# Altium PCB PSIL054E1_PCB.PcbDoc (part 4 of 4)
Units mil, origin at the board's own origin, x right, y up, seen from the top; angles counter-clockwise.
Board outline 2080 x 2700 mil, 8 copper layers (SSTXRX1, GND Plane 1, High Speed, GND Plane 2, Power 1, Power 2, GND Plane 3, SSTXRX2), stack 58.12 mil thick; 247 components, 148 nets, 834 pads, 632 vias.
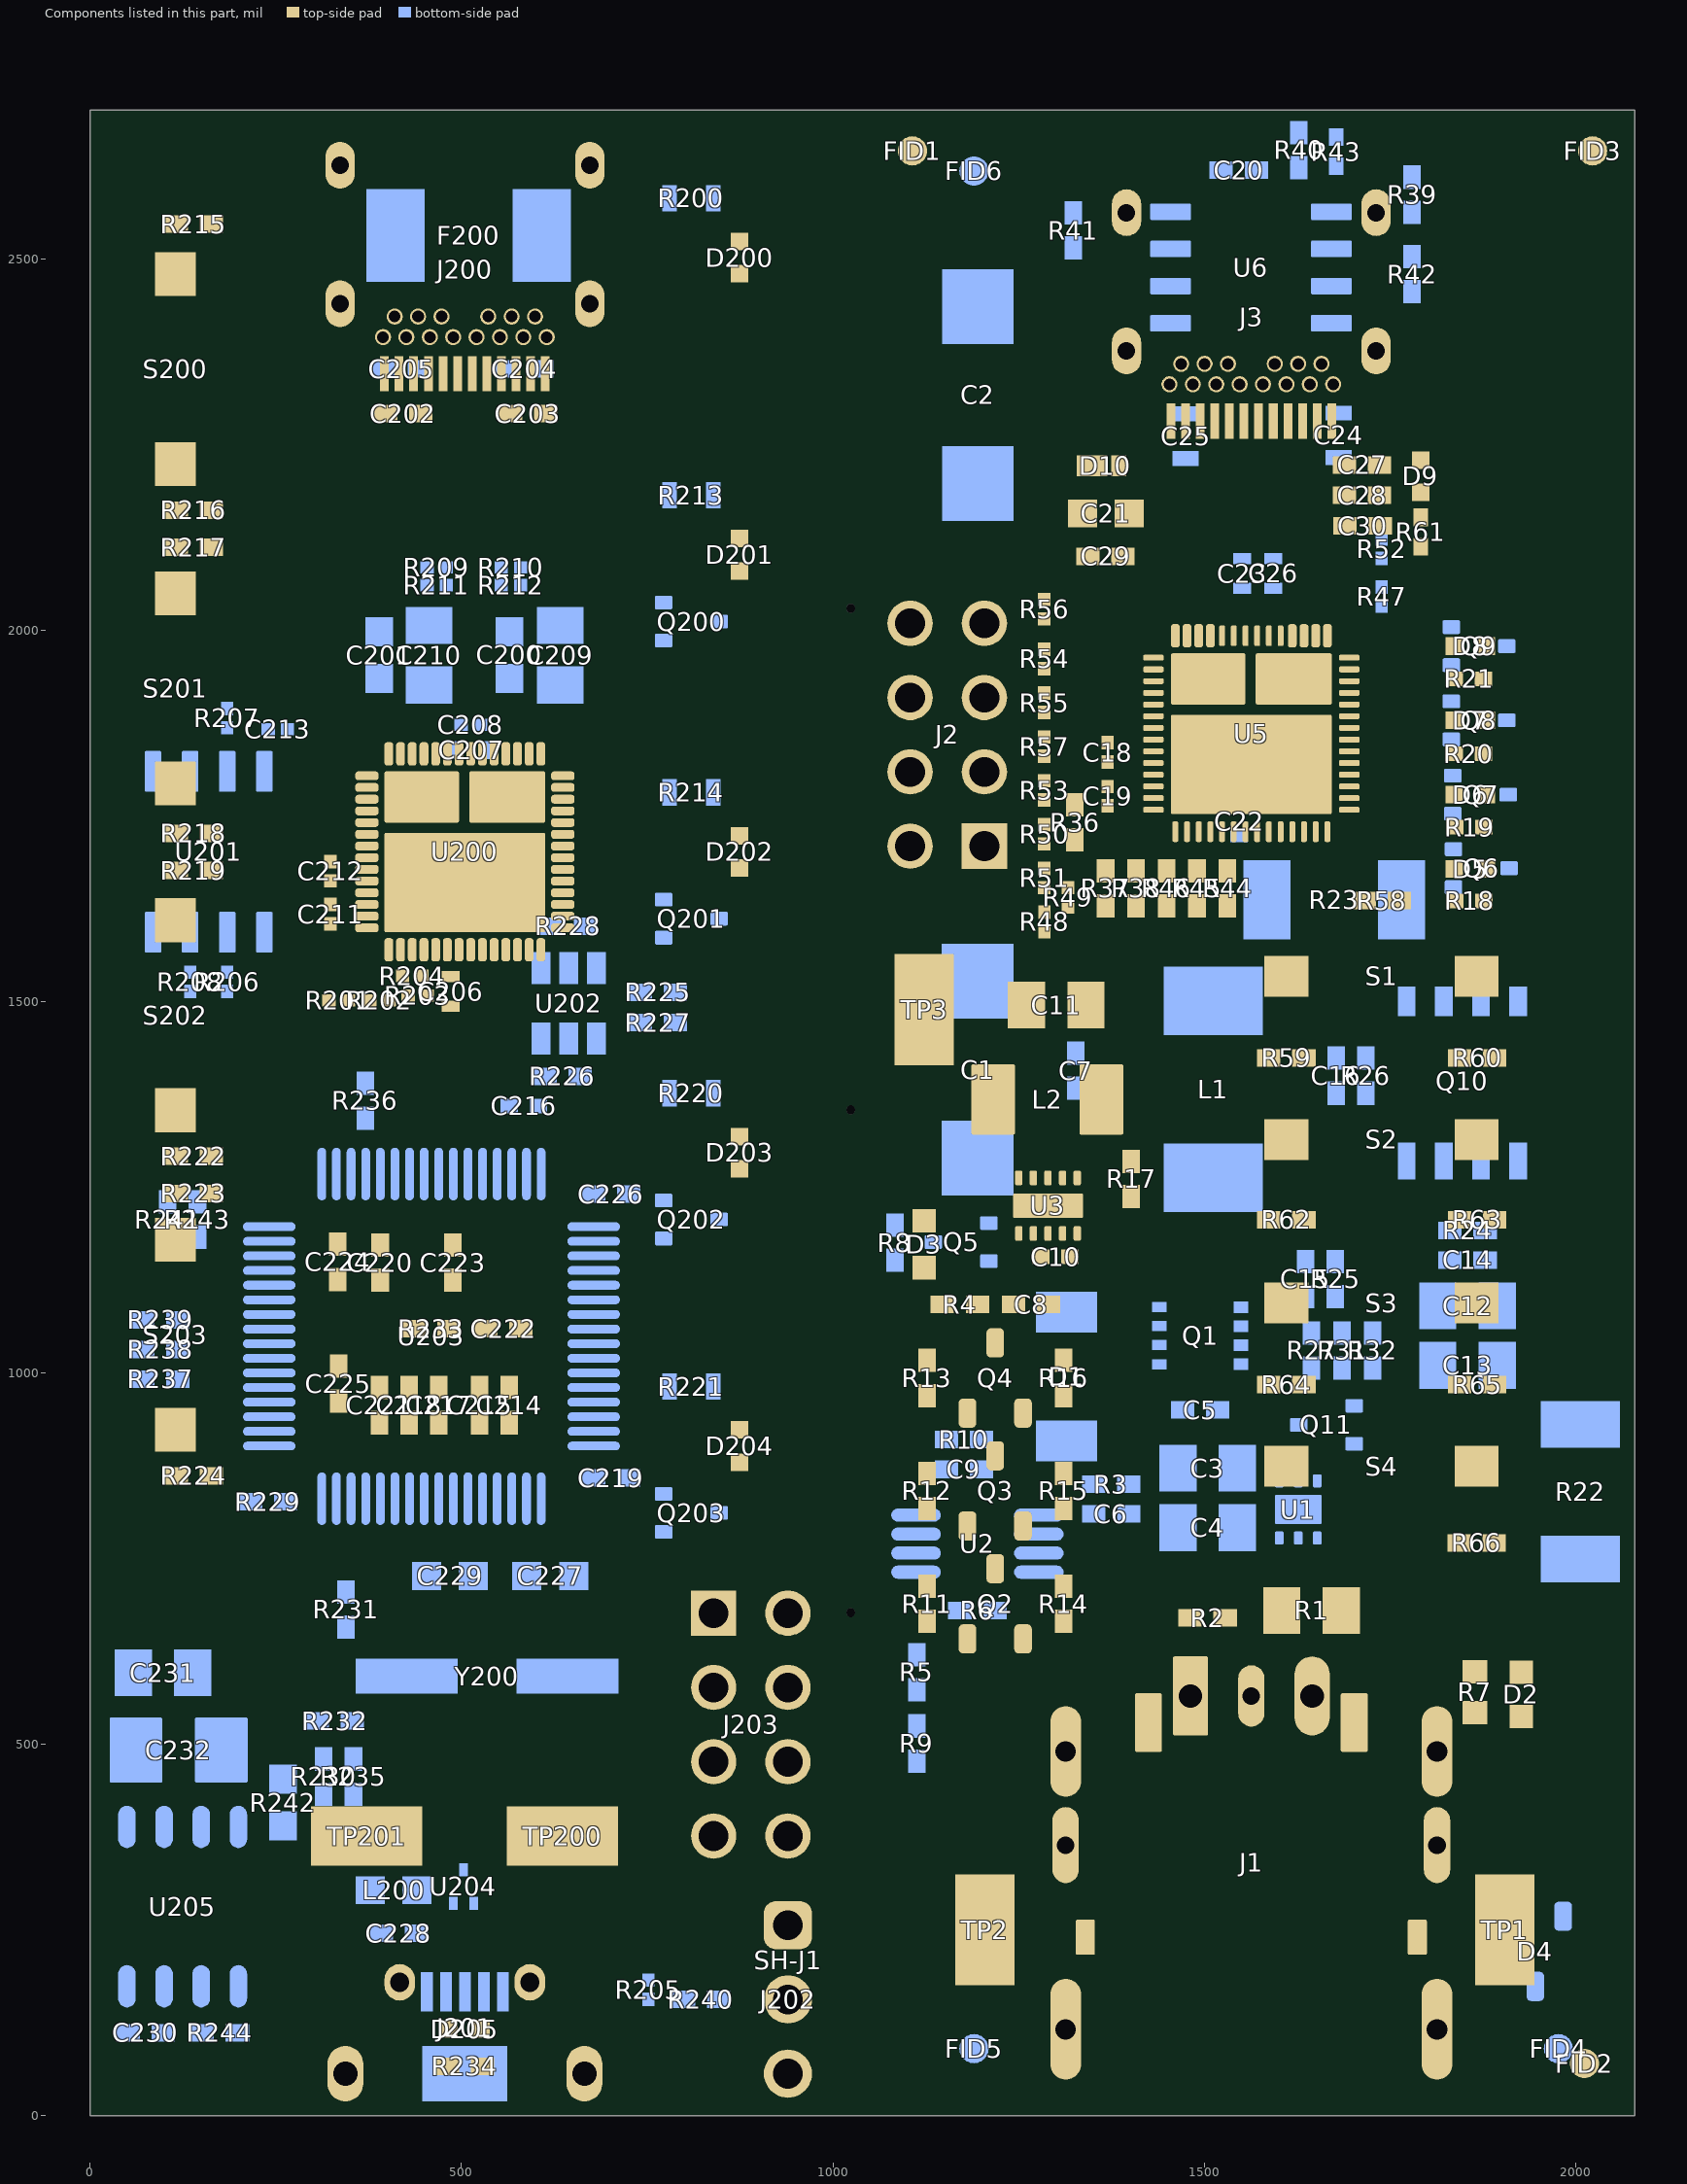
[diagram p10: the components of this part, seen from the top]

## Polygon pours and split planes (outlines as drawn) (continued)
P3V3_SINK on Power 1 "POWER_1_P3V3_SINK_P162" (solid, remove dead copper, pour order 162): 235.45,1211.31 412.45,1388.31 579.45,1388.31 634.45,1333.31 634.45,906.31 251.45,906.31 235.45,922.31
P3V3_SINK on Power 1 "POWER_1_P3V3_SINK_P160" (solid, remove dead copper, pour order 160): 14.45,641.31 0,655.75 0,2663.86 36.14,2700 970,2700 1000,2670 1000,1528.86 902.45,1431.31 819.45,1431.31 803.45,1447.31 804.45,1448.31 804.45,2411.31 758.45,2457.31 364.45,2457.31 228.45,2593.31 135.45,2593.31 113,2570.86 113,647.47
GND on High Speed "HIGH_SPEED_GND_P188" (solid, remove dead copper, pour order 188): 0,2700 2080,2700 2080,0 0,0
SYS_PWR on High Speed "HIGH_SPEED_SYS_PWR_P082" (solid, remove dead copper, pour order 82): 1365,732 2072,732 2072,636 1914,478 1365,478
NetC12_1 on High Speed "HIGH_SPEED_NETC12_1_P076" (solid, remove dead copper, pour order 76): 1877,1529.93 2004.66,1529.93 2072,1462.59 2072,889.93 1894.66,889.93 1877,907.59 1877,1203.93
PP_HV on High Speed "HIGH_SPEED_PP_HV_P062" (solid, remove dead copper, pour order 62): 1436,1456 1159.79,1456 1055,1560.79 1055,2181 1615.26,2181 1647.1,2149.16 1692.35,2149.16 1754.37,2087.13 1754.37,1966.76 1386.51,1966.76 1372.75,1953 1376,1949.75 1376,1838 1436,1778
VREGOUT on High Speed "HIGH_SPEED_VREGOUT_P182" (solid, remove dead copper, pour order 182): 694.45,816.31 689.45,811.31 459.45,811.31 378.64,892.12 378.64,1200.5 459.45,1281.31 689.45,1281.31 694.45,1276.31
VBUS_SINK on High Speed "HIGH_SPEED_VBUS_SINK_P180" (solid, remove dead copper, pour order 180): 557.45,2208.31 663.45,2102.31 663.45,1825.31 646.45,1808.31 209.45,1808.31 183.45,1834.31 183.45,1980.31 411.45,2208.31
VBUS_SINK on High Speed "HIGH_SPEED_VBUS_SINK_P178" (solid, remove dead copper, pour order 178): 219.45,2389.31 219.45,2657.31 262.14,2700 750.75,2700 851.45,2599.31 851.45,2139.31 825.45,2113.31 716.45,2113.31 624.45,2205.31 624.45,2420.31 584.45,2460.31 380.45,2460.31 328.45,2408.31 329.45,2407.31 329.45,2263.31 270.45,2204.31 235.45,2204.31 218.45,2221.31
GND on Power 2 "POWER_2_GND_P184" (solid, remove dead copper, pour order 184): 0,2700 2080,2700 2080,0 0,0
SYS_PWR on Power 2 "POWER_2_SYS_PWR_P078" (solid, remove dead copper, pour order 78): 1365,732 2072,732 2072,636 1914,478 1365,478
NetC12_1 on Power 2 "POWER_2_NETC12_1_P072" (solid, remove dead copper, pour order 72): 1877,1529.93 2004.66,1529.93 2072,1462.59 2072,889.93 1894.66,889.93 1877,907.59 1877,1203.93
PP_HV on Power 2 "POWER_2_PP_HV_P058" (solid, remove dead copper, pour order 58): 1436,1456 1159.79,1456 1055,1560.79 1055,2181 1615.26,2181 1647.1,2149.16 1692.35,2149.16 1754.37,2087.13 1754.37,1966.76 1386.51,1966.76 1372.75,1953 1376,1949.75 1376,1838 1436,1778
PP_HV_SINK on Power 2 "POWER_2_PP_HV_SINK_P174" (solid, remove dead copper, pour order 174): 810.45,1719.31 810.45,2075.31 709.45,2176.31 419.45,2176.31 254.45,2011.31 254.45,1719.31
PP_HV_SINK on Power 2 "POWER_2_PP_HV_SINK_P172" (solid, remove dead copper, pour order 172): 797.75,1823 866.45,1754.31 866.45,448.31 714.45,296.31 124.45,296.31 0,420.75 0,1621.86 201.14,1823
FUSE_VBUS on Power 2 "POWER_2_FUSE_VBUS_P170" (solid, remove dead copper, pour order 170): 750.75,2700 881.45,2569.31 881.45,2316.31 827.45,2262.31 106.45,2262.31 47.45,2321.31 47.45,2589.31 158.14,2700
GND on GND Plane 1 (split plane): 2059.9,20.1 1788.32,20.1 1788.32,466.47 1788.32,469.6 1787.94,473.52 1786.79,477.29 1784.39,483.08 1782.54,486.55 1780.04,489.6 1775.61,494.03 1772.56,496.53 1769.09,498.38 1763.3,500.78 1759.53,501.92 1755.61,502.31 1752.48,502.31 1374.52,502.31 1371.39,502.31 1367.47,501.92 1363.7,500.78 1357.91,498.38 1354.44,496.53 1351.39,494.03 1346.96,489.6 1346.07,488.5 1344.46,486.55 1342.61,483.08 1340.21,477.29 1339.87,476.17 1339.07,473.52 1338.81,470.88 1338.68,469.6 1338.68,466.47 1338.68,20.1 1046.15,20.1 1048.21,21.79 1050.71,24.83 1052.57,28.31 1053.71,32.08 1054.1,36 1054.1,641 1053.71,644.92 1052.57,648.69 1050.71,652.17 1048.21,655.21 1045.17,657.71 1041.69,659.57 1037.92,660.71 1034,661.1 1014,661.1 1010.08,660.71 1006.31,659.57 1002.83,657.71 999.79,655.21 997.29,652.17 995.43,648.69 994.29,644.92 993.9,641 993.9,36 994.29,32.08 995.43,28.31 997.29,24.83 999.79,21.79 1001.85,20.1 20.1,20.1 20.1,2679.9 998.72,2679.9 997.29,2678.17 995.43,2674.69 994.29,2670.92 993.9,2667 993.9,2062 994.29,2058.08 995.43,2054.31 997.29,2050.83 999.79,2047.79 1002.83,2045.29 1006.31,2043.43 1010.08,2042.29 1014,2041.9 1034,2041.9 1037.92,2042.29 1041.69,2043.43 1045.17,2045.29 1048.21,2047.79 1050.71,2050.83 1052.57,2054.31 1053.71,2058.08 1054.1,2062 1054.1,2667 1053.71,2670.92 1052.57,2674.69 1050.71,2678.17 1049.28,2679.9 2059.9,2679.9
GND on GND Plane 2 (split plane): 2059.9,20.1 1788.32,20.1 1788.32,466.47 1788.32,469.6 1787.94,473.52 1786.79,477.29 1784.39,483.08 1782.54,486.55 1780.04,489.6 1775.61,494.03 1772.56,496.53 1769.09,498.38 1763.3,500.78 1759.53,501.92 1755.61,502.31 1752.48,502.31 1374.52,502.31 1371.39,502.31 1367.47,501.92 1363.7,500.78 1357.91,498.38 1354.44,496.53 1351.39,494.03 1346.96,489.6 1346.07,488.5 1344.46,486.55 1342.61,483.08 1340.21,477.29 1339.87,476.17 1339.07,473.52 1338.81,470.88 1338.68,469.6 1338.68,466.47 1338.68,20.1 1046.15,20.1 1048.21,21.79 1050.71,24.83 1052.57,28.31 1053.71,32.08 1054.1,36 1054.1,641 1053.71,644.92 1052.57,648.69 1050.71,652.17 1048.21,655.21 1045.17,657.71 1041.69,659.57 1037.92,660.71 1034,661.1 1014,661.1 1010.08,660.71 1006.31,659.57 1002.83,657.71 999.79,655.21 997.29,652.17 995.43,648.69 994.29,644.92 993.9,641 993.9,36 994.29,32.08 995.43,28.31 997.29,24.83 999.79,21.79 1001.85,20.1 20.1,20.1 20.1,2679.9 998.72,2679.9 997.29,2678.17 995.43,2674.69 994.29,2670.92 993.9,2667 993.9,2062 994.29,2058.08 995.43,2054.31 997.29,2050.83 999.79,2047.79 1002.83,2045.29 1006.31,2043.43 1010.08,2042.29 1014,2041.9 1034,2041.9 1037.92,2042.29 1041.69,2043.43 1045.17,2045.29 1048.21,2047.79 1050.71,2050.83 1052.57,2054.31 1053.71,2058.08 1054.1,2062 1054.1,2667 1053.71,2670.92 1052.57,2674.69 1050.71,2678.17 1049.28,2679.9 2059.9,2679.9
GND on GND Plane 3 (split plane): 2059.9,20.1 1788.32,20.1 1788.32,466.47 1788.32,469.6 1787.94,473.52 1786.79,477.29 1784.39,483.08 1782.54,486.55 1780.04,489.6 1775.61,494.03 1772.56,496.53 1769.09,498.38 1763.3,500.78 1759.53,501.92 1755.61,502.31 1752.48,502.31 1374.52,502.31 1371.39,502.31 1367.47,501.92 1363.7,500.78 1357.91,498.38 1354.44,496.53 1351.39,494.03 1346.96,489.6 1346.07,488.5 1344.46,486.55 1342.61,483.08 1340.21,477.29 1339.87,476.17 1339.07,473.52 1338.81,470.88 1338.68,469.6 1338.68,466.47 1338.68,20.1 1046.15,20.1 1048.21,21.79 1050.71,24.83 1052.57,28.31 1053.71,32.08 1054.1,36 1054.1,641 1053.71,644.92 1052.57,648.69 1050.71,652.17 1048.21,655.21 1045.17,657.71 1041.69,659.57 1037.92,660.71 1034,661.1 1014,661.1 1010.08,660.71 1006.31,659.57 1002.83,657.71 999.79,655.21 997.29,652.17 995.43,648.69 994.29,644.92 993.9,641 993.9,36 994.29,32.08 995.43,28.31 997.29,24.83 999.79,21.79 1001.85,20.1 20.1,20.1 20.1,2679.9 998.72,2679.9 997.29,2678.17 995.43,2674.69 994.29,2670.92 993.9,2667 993.9,2062 994.29,2058.08 995.43,2054.31 997.29,2050.83 999.79,2047.79 1002.83,2045.29 1006.31,2043.43 1010.08,2042.29 1014,2041.9 1034,2041.9 1037.92,2042.29 1041.69,2043.43 1045.17,2045.29 1048.21,2047.79 1050.71,2050.83 1052.57,2054.31 1053.71,2058.08 1054.1,2062 1054.1,2667 1053.71,2670.92 1052.57,2674.69 1050.71,2678.17 1049.28,2679.9 2059.9,2679.9

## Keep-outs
Keep-Out Layer:
  text ".Layer_Name" at 577,-858.49 h60

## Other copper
SSTXRX1:
  rectangle net SYS_PWR: 1859.66,170.93 1948.66,434.93
  rectangle net GND: 1159.66,168.93 1249.66,435.93
  rectangle net GND: 1650.1,1785.26 1703.1,1827.26
  region net P3V3: 1172.66,1563.93 1092.66,1563.93 1092.66,1345.93 1172.66,1345.93
  rectangle net SYS_PWR: 1259.66,1144.93 1295.66,1202.93
  rectangle net GND: 1304.66,1144.93 1339.66,1240.93
  region net NetD205_2: 514.45,128.12 514.45,54.31 544.45,54.31 544.45,128.12
  region net NetD204_1: 858.7,999.31 858.7,919.31 890.45,919.31 890.45,999.31
  region net NetD203_1: 858.7,1394.31 858.7,1315.31 890.45,1315.31 890.45,1394.31
  region net NetD202_1: 858.7,1799.31 858.7,1719.31 890.45,1719.31 890.45,1799.31
  region net NetD201_1: 858.7,2199.31 858.7,2119.31 890.45,2119.31 890.45,2199.31
  region net NetD200_1: 858.7,2600.31 858.7,2519.31 890.45,2519.31 890.45,2600.31
  region net GND: 598.45,1668.31 598.45,1624.31 652.45,1624.31 652.45,1668.31
  region net LDO_3V3_SINK: 144.45,1261.31 144.45,1221.31 209.45,1221.31 209.45,1261.31
  region net LDO_3V3_SINK: 144.45,1696.31 144.45,1656.31 209.45,1656.31 209.45,1696.31
  region net LDO_3V3_SINK: 144.45,2131.31 144.45,2091.31 209.45,2091.31 209.45,2131.31
  region net LDO_3V3_SINK: 144.45,2566.31 144.45,2526.31 209.45,2526.31 209.45,2566.31
  text ".Layer_Name" at 577,-859.49 h60
High Speed:
  text ".Layer_Name" at 577,-858.49 h60
Power 1:
  text ".Layer_Name" at 577,-859.49 h60
Power 2:
  text ".Layer_Name" at 577,-858.49 h60
SSTXRX2:
  rectangle net DRAIN2: 1572,1899 1675,1968
  rectangle net DRAIN1: 1461,1897 1563,1968
  rectangle net Drain2_SINK: 515,1745 610,1805
  rectangle net Drain1_SINK: 400,1745 495,1805
  region net F_I2C1_SDA: 209.45,1117.88 209.45,1096.31 274.45,1096.31 274.45,1117.88
  region net VBUS_SINK: 746.45,2599.31 746.45,2563.31 789.45,2563.31 789.45,2599.31
  region net NetD200_1: 828.45,2599.31 828.45,2563.31 882.45,2563.31 882.45,2599.31
  region net NetD201_1: 829.45,2199.31 829.45,2163.31 882.45,2163.31 882.45,2199.31
  region net LDO_3V3_SINK: 746.45,2199.31 746.45,2163.31 790.45,2163.31 790.45,2199.31
  region net NetD202_1: 828.45,1799.31 828.45,1763.31 882.45,1763.31 882.45,1799.31
  region net LDO_3V3_SINK: 746.45,1799.31 746.45,1763.31 790.45,1763.31 790.45,1799.31
  region net LDO_3V3_SINK: 746.45,1394.31 746.45,1358.31 790.45,1358.31 790.45,1394.31
  region net NetD203_1: 828.45,1394.31 828.45,1358.31 882.45,1358.31 882.45,1394.31
  region net NetD204_1: 828.45,999.31 828.45,963.31 882.45,963.31 882.45,999.31
  region net LDO_3V3_SINK: 746.45,999.31 746.45,963.31 789.45,963.31 789.45,999.31
  text ".Layer_Name" at 577,-858.49 h60
  text ".Layer_Name" at 577,-859.49 h60
GND Plane 1 (plane layer: these items are gaps in the copper):
  text ".Layer_Name" at 577,-858.49 h60
GND Plane 2 (plane layer: these items are gaps in the copper):
  text ".Layer_Name" at 577,-858.49 h60
GND Plane 3 (plane layer: these items are gaps in the copper):
  text ".Layer_Name" at 577,-858.49 h60

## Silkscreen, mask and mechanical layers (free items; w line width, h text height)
Top Overlay:
  lines w10: 4.45,751.31 997,751 ; 859,155 859,14 939,14 ; 897,156 859,156 859,300 938,300
  text "TIDA-050012" at 1177,2671 h100 r270
  text "VBUS" at 919.45,2621.31 h100 r270
  text "D5 - D8: Output Voltage / S1 - S4: Source Voltage Select" at 1915,2577 h50 r270
  text "5V" at 205,2405 h100 r270
  text "VBUS" at 1852,2248 h60 r270
  text "5V" at 915,2140 h100 r270
  text "D200 - D203: Input Voltage / S200 - S203: Sink Voltage Select" at 666,2130 h50 r270
  text "20V" at 1918,2049 h70 r270
  text "9V" at 204.45,1971.31 h100 r270
  text "15V" at 1919,1930 h70 r270
  text "9V" at 1919,1811 h70 r270
  text "9V" at 915,1740 h100 r270
  text "5V" at 1919,1715 h70 r270
  text "5V" at 1937,1588 h100 r270
  text "15V" at 204.45,1571.31 h100 r270
  text "3.3V" at 1101,1389 h60 r270
  text "9V" at 1937,1363 h100 r270
  text "15V" at 915,1360 h100 r270
  text "DC/DC Output" at 1062,1295 h30 r270
  text "15V" at 1936,1170 h100 r270
  text "20V" at 205,1120 h100 r270
  text "20V" at 915,960 h100 r270
  text "20V" at 1935,956 h100 r270
  text "PPHV" at 610,685 h100 r270
  text "TIDA-050014" at 93,666 h100 r270
  text "GND" at 342,636 h100 r270
  text "SYS_PWR" at 1992,373 h60 r270
  text "GND" at 1084,303 h60 r270
  text "SNK" at 785,300 h70 r270
  text "SRC" at 785,145 h70 r270
  text ".Layer_Name" at 577,-858.49 h60
Bottom Overlay:
  region: 147,2167 147,2467 47,2467 47,2167
  text "PSIL054E1" at 203,2103 h108.27 r270
  text ".Layer_Name" at 577,-858.49 h60
Top Paste:
  text ".Layer_Name" at 577,-858.49 h60
Bottom Paste:
  text ".Layer_Name" at 577,-858.49 h60
Top Solder:
  text ".Layer_Name" at 577,-858.49 h60
  text ".Layer_Name" at 577,-858.49 h60
Bottom Solder:
  text ".Layer_Name" at 577,-858.49 h60
Drill Guide:
  text ".Layer_Name" at 577,-858.49 h60
M1 Board Outline:
  lines w10: 1075,2802 1386,3174 ; 0,0 2080,0 2080,2700 0,2700 0,0 ; 1038,2761 1099,2771 1046,2832 1038,2761
  lines w20: 1024,46 1024,631 ; 1024,723 1024,1308 ; 1024,1401 1024,1986 ; 1024,2072 1024,2657
  text "Routed Slots 20 mils wide x 4 places" at 1392,3186 h72.83
  text ".Layer_Name" at 577,-858.49 h60
M2 Board Dimensions:
  rectangle: 125,-400 500,-275
  rectangle: 0,-275 125,-150
  lines w7: 0,-275 1000,-275 ; 125,-400 125,-150 ; 250,-400 250,-150 ; 500,-400 500,-150 ; 750,-400 750,-150 ; 0,-400 0,-150 1000,-150 1000,-400 0,-400
  text ".Layer_Name" at 577,-858.49 h60
M3 3D STEP Top:
  text ".Layer_Name" at 577,-858.49 h60
M4 3D STEP Bottom:
  text ".Layer_Name" at 577,-858.49 h60
M5 Assembly Top:
  lines w10: -292,-930.17 6308,-930.17 ; -292,-726.83 6310,-726.83 ; -292,-523.5 -292,-1133.5 3713,-1133.5 6310,-1133.5 6310,-523.5 -291.5,-523.5 -291.5,-1133.5 1284,-1133.5 ; 2173,-1133.5 2173,-523.5 ; 3440,-726.83 3440,-523.5 ; 4280,-726.83 4280,-523.5 ; 4902,-1140 4902,-937.17
  text "COMPONENTS MARKED 'DNP' SHOULD NOT BE POPULATED." at 1153.5,-318.5 h60
  text "ASSEMBLY VARIANT:" at 1153,-434 h60
  text ".VariantName" at 2189,-434 h60
  text "PCB VIEWED FROM TOP SIDE" at -228.5,-655.67 h60
  text "BOARD #:" at 2248,-655.67 h60
  text ".PRJ_Number" at 2793.5,-655.67 h60
  text "REV:" at 3638,-655.67 h60
  text ".PCB_Rev" at 3929.5,-655.67 h60
  text "SVN REV:" at 4476,-655.67 h60
  text ".VersionControl_RevNumber" at 4982,-655.67 h60
  text "TID #:" at 2248,-859 h60
  text ".TID" at 2793.5,-859 h60
  text "PLOT NAME =" at -228.5,-1064.34 h60
  text ".plot_File_Name" at 577,-1064.34 h60
  text "GENERATED    :" at 2250,-1064.34 h60
  text ".Print_Date" at 3119.5,-1064.34 h60
  text ".Print_Time" at 3848.5,-1064.34 h60
  text "TEXAS INSTRUMENTS" at 5113,-1064.34 h60
M6 Assembly Bottom:
  lines w10: -292.5,-727.33 6309.5,-727.33 ; -290.5,-930.67 6309.5,-930.67 ; 1115.5,-1140.5 1115.5,-937.67 ; 1737.5,-727.33 1737.5,-524 ; 2577.5,-727.33 2577.5,-524 ; 3844.5,-1134 3844.5,-524 ; 4733.5,-1134 6309,-1134 6309,-524 -292.5,-524 -292.5,-1134 2304.5,-1134 6309.5,-1134 6309.5,-524
  text "COMPONENTS MARKED 'DNP' SHOULD NOT BE POPULATED." at 6102,-318 h60
  text ".VariantName" at 5058,-434 h60
  text "ASSEMBLY VARIANT:" at 6097,-434 h60
  text ".VersionControl_RevNumber" at 1035.5,-656.17 h60
  text "SVN REV:" at 1541.5,-656.17 h60
  text ".PCB_Rev" at 2088,-656.17 h60
  text "REV:" at 2379.5,-656.17 h60
  text ".PRJ_Number" at 3224,-656.17 h60
  text "BOARD #:" at 3769.5,-656.17 h60
  text "PCB VIEWED FROM BOTTOM SIDE" at 6246,-656.17 h60
  text ".TID" at 3224,-859.5 h60
  text "TID #:" at 3769.5,-859.5 h60
  text "TEXAS INSTRUMENTS" at 904.5,-1064.84 h60
  text ".Print_Time" at 2169,-1064.84 h60
  text ".Print_Date" at 2898,-1064.84 h60
  text "GENERATED    :" at 3767.5,-1064.84 h60
  text ".plot_File_Name" at 5440.5,-1064.84 h60
  text "PLOT NAME =" at 6246,-1064.84 h60
M9 Title Sheet:
  drawing of 57 lines, arcs and shapes, not listed
  text "1" at 739.84,8036.5 h70
  text "2" at 3235.5,8036.5 h70
  text "3" at 5724.84,8036.5 h70
  text "4" at 8231.51,8036.5 h70
  text "5" at 10730.5,8036.5 h70
  text "6" at 13235.5,8036.5 h70
  text "A" at -416.5,6893.5 h70
  text "A" at 14383.5,6893.5 h70
  text "B" at -416.5,4513.5 h70
  text "B" at 14383.5,4513.5 h70
  text "C" at -416.5,2138.5 h70
  text "C" at 14383.5,2138.5 h70
  text "PROJECT TITLE:" at 11343.5,277.5 h45
  text ".PRJ_Title" at 11393.5,144.17 h70
  text "DESIGNED FOR:" at 11343.5,-23.5 h45
  text ".PRJ_Customer" at 11393.5,-163.5 h70
  text "D" at -416.5,-231.5 h70
  text "D" at 14383.5,-231.5 h70
  text "FILE NAME:" at 11343.5,-323.5 h45
  text ".PCB_File_Name_No_Path" at 11393.5,-443.5 h70
  text "Texas Instruments (TI) and/or its licensors do not warrant the accuracy or completeness of this specification" at 6374,-605.34 h45
  text "ENGINEER:" at 11343.5,-613.5 h45
  text "LAYOUT BY:" at 12848.5,-613.5 h45
  text "or any information contained therein. TI and/or its licensors do not warrant that this design will meet" at 6329.01,-718 h45
  text ".PRJ_Engineer" at 11393.5,-768.49 h70
  text ".PCB_Layout" at 12899,-768.49 h70
  text "the specifications, will be suitable for your application or fit for any particular purpose, or will operate in" at 6329.01,-830.67 h45
  text ".Layer_Name" at 577,-858.49 h60
  text "ALTIUM DESIGNER VERSION:" at 12848.5,-923.5 h45
  text "an implementation. TI and/or its licensors do not warrant that the design is production worthy. You should" at 6329.01,-943.33 h45
  text "completely validate and test your design implementation to confirm the system functionality for your application." at 6374,-1056 h45
  text ".print_Scale" at 11393.5,-1056.83 h70
  text ".Application_BuildNumber" at 12899,-1056.83 h70
  text "1" at 739.84,-1263.5 h70
  text "2" at 3235.5,-1263.5 h70
  text "3" at 5724.84,-1263.5 h70
  text "4" at 8231.51,-1263.5 h70
  text "5" at 10730.5,-1263.5 h70
  text "6" at 13235.5,-1263.5 h70
M10 Fab Notes:
  drawing of 189 lines, arcs and shapes, not listed
  text "DESIGN INFORMATION" at 12382.02,6356.17 h60
  text "MIN. TRACK WIDTH:" at 11737.46,6224.05 h60
  text "4" at 12833.7,6224.05 h60
  text "MIL" at 12988.46,6224.05 h60
  text "0.0762" at 12695,6101 h60
  text "MIN. CLEARANCE:" at 11737.46,6099.92 h60
  text "mm" at 13063,6098 h60
  text "MIN. VIA PAD SIZE:" at 11737.46,5975.8 h60
  text "4" at 12803.71,5975.8 h60
  text "MIL" at 12988.46,5975.8 h60
  text "0.05mm (2MIL)" at 12432.46,5845.9 h60
  text "MINIMUM ANNULAR RING" at 11408.23,5837.67 h60
  text "EXTERNAL" at 13140.46,5837.67 h60
  text "PER" at 11608.23,5727.55 h60
  text "IPC-D-275 CLASS 2 LEVEL C" at 11828.23,5727.54 h60
  text "MIL, HOLES" at 13316.46,5627.07 h60
  text "+/-" at 12924,5618.48 h60
  text "+/-" at 13778,5618.48 h60
  text "REGISTRATION TOLERANCES:" at 11408.23,5617.42 h60
  text "METAL" at 12608,5617.42 h60
  text "5" at 13184.2,5617.42 h60
  text "3" at 14017.2,5617.42 h60
  text "MIL" at 14133.46,5617.42 h60
  text "HOLE SIZE TOLERANCE (UNLESS OTHERWISE SPECIFIED):" at 11408.23,5519.1 h60
  text "+/-" at 13778,5516.23 h60
  text "3" at 14017.2,5515.17 h60
  text "MIL" at 14133.46,5515.17 h60
  text "MATERIAL:" at 11333.46,5377.52 h60
  text "FR-4 High Tg" at 12319.9,5249 h60
  text "X" at 12175.46,5241.01 h60
  text "FR-408" at 11754.46,5236.49 h60
  text "OTHER" at 13242.46,5236.49 h60
  text "62 MIL (1.6mm) +/-10%" at 12074.56,5093.46 h60
  text "X" at 11954.46,5091.01 h60
  text "THICKNESS:" at 11408.23,5085.24 h60
  text "OTHER" at 13359.46,5085.24 h60
  text "TOLERANCE:" at 11408.23,4946.92 h60
  text "X" at 12256.46,4946.92 h60
  text "ANSI IPC-6012 TYPE 3 CLASS 2" at 12434.48,4946.92 h60
  text "OTHER +/-" at 12434.46,4802.73 h60
  text "BOW & TWIST:" at 11408.23,4657.54 h60
  text "X" at 12256.46,4657.54 h60
  text "ANSI IPC-6012 TYPE 3 CLASS 2" at 12434.48,4657.54 h60
  text "OTHER +/-" at 12434.46,4510.85 h60
  text "DRILLING:" at 11333.46,4380.23 h60
  text "NC_DRILL FILES" at 13094.46,4275.04 h60
  text "REFERENCE:" at 11408.23,4271.1 h60
  text "X" at 12065.46,4271.01 h60
  text "AS SHOWN" at 12243.46,4271.1 h60
  text "X" at 12966.46,4271.1 h60
  text "OTHER" at 13392.46,4128.85 h60
  text "PTH COPPER THICKNESS:" at 11407.91,4125.32 h60
  text "X" at 12547.14,4125.32 h60
  text "20-30 um" at 12675.14,4125.32 h60
  text "BOARD FINISH:" at 11333.46,3977.73 h60
  text "SILKSCREEN:" at 11488.68,3867.6 h60
  text "X" at 12446.46,3867.6 h60
  text "TOP" at 12563.46,3867.6 h60
  text "X" at 12956.46,3867.6 h60
  text "BOTTOM" at 13074.46,3867.6 h60
  text "SILKSCREEN COLOR:" at 11488.68,3712.41 h60
  text "X" at 12445.46,3712.41 h60
  text "WHITE" at 12563.46,3712.41 h60
  text "OTHER" at 13074.46,3712.41 h60
  text "Black" at 13647,3574 h60
  text "X" at 13163.46,3571.71 h60
  text "GREEN" at 12694.46,3568.96 h60
  text "OTHER" at 13312.46,3568.96 h60
  text "SOLDER RESIST COLOR:" at 11488.68,3562.1 h60
  text "X" at 12576.46,3414.71 h60
  text "MATTE" at 12694.46,3414.71 h60
  text "SEMI-GLOSS" at 13312,3414.07 h60
  text "IMMERSION GOLD (ENIG)" at 12394.46,3241.94 h60
  text "ENEPIG" at 13732,3234.72 h60
  text "SURFACE FINISH:" at 11333.46,3233.72 h60
  text "X" at 12216.46,3233.72 h60
  text "IMM. TIN/SILVER OR EQUIV" at 11663,3096.4 h60
  text "OTHER" at 13094.46,3092.47 h60
  text "ARRAY/PANEL:" at 11333.46,2937.09 h60
  text "CUT AND TRIM PER M1 BOARD OUTLINE" at 12394.46,2928.87 h60
  text "N.C. ROUTE" at 12394.46,2792.9 h60
  text "X" at 13082.46,2792.9 h60
  text "V. SCORE" at 13260.46,2792.9 h60
  text "CERTIFICATION:" at 11333.46,2663.77 h60
  text "MATERIALS AND WORKMANSHIP FOR ALL PCBS" at 12058.46,2663.77 h60
  text "TO MEET OR EXCEED THE REQUIREMENTS OF:" at 12058.46,2569.71 h60
  text "X" at 11695.97,2441.08 h60
  text "ANSI IPC-A-600F CLASS ->" at 11823.96,2441.08 h60
  text "X" at 13471.97,2441.08 h60
  text "2" at 13581.96,2441.08 h60
  text "1" at 13266.96,2439.58 h60
  text "3" at 13935.96,2439.58 h60
  text "X" at 12507.97,2293.39 h60
  text "RoHS" at 12635.96,2293.39 h60
  text "OTHER" at 13280.36,2293.39 h60
  text "PER ORDER" at 13677.42,2293.39 h60
  text "ALL BOARDS MUST MEET OR EXCEED UL94-V0 REQUIREMENTS." at 11361,2139.57 h60
  text "PCB MUST BEAR THE UL94V-0 UL REGISTERED MATERIAL ID NUMBER" at 11361,2023.5 h60
  text "ADDITIONAL REQUIREMENTS:" at 11333.46,1854.08 h60
  text "MICROSECTION:" at 11408.23,1746.95 h60
  text "YES" at 12313.96,1746.95 h60
  text "REQUIRED" at 13175.46,1602.62 h60
  text "BARE BOARD ELEC. TEST:" at 11408.23,1599.76 h60
  text "NONE" at 12713.96,1599.76 h60
  text "X" at 13057.46,1599.76 h60
  text "PER ORDER" at 13767.46,1599.76 h60
  text "XX MIL VIAS REQUIRE NON-CONDUCTIVE FILL AND PLANARIZE" at 11576.38,1394.82 h59
  text "XX MIL VIAS REQUIRE CONDUCTIVE FILL AND PLANARIZE" at 11584.38,1290.84 h60
  text "OUTER XX MIL VIAS REQUIRE 50 OHM SINGLE-ENDED IMPEDANCE" at 11583.39,1127.46 h58
  text "All Vias on Pads: Epoxy fill and plate" at 5340,1071 h120
  text "LAYER 2 & 3 (INNER LAYERS) XX MIL WIDE, XX MIL SPACE / TRACES REQUIRE 100 OHM DIFFERENTIAL IMPEDANCE" at 11575.39,891.74 h60
  text ".Layer_Name" at 577,-858.49 h60
M11 Gerber Information:
  lines w10: -292,-930.17 6308,-930.17 ; -292,-726.83 6310,-726.83 ; -292,-523.5 -292,-1133.5 3713,-1133.5 6310,-1133.5 6310,-523.5 -291.5,-523.5 -291.5,-1133.5 1284,-1133.5 ; 2173,-1133.5 2173,-523.5 ; 3440,-726.83 3440,-523.5 ; 4280,-726.83 4280,-523.5 ; 4902,-1140 4902,-937.17
  text "ALL ARTWORK VIEWED FROM TOP SIDE" at -228.5,-655.67 h60
  text "BOARD #:" at 2248,-655.67 h60
  text ".PRJ_Number" at 2793.5,-655.67 h60
  text "REV:" at 3638,-655.67 h60
  text ".PCB_Rev" at 3929.5,-655.67 h60
  text "SVN REV:" at 4476,-655.67 h60
  text ".VersionControl_RevNumber" at 4982,-655.67 h60
  text "LAYER NAME =" at -228.5,-858.49 h60
  text "TID #:" at 2248,-859 h60
  text ".TID" at 2793.5,-859 h60
  text "PLOT NAME =" at -228.5,-1064.34 h60
  text ".plot_File_Name" at 577,-1064.34 h60
  text "GENERATED    :" at 2250,-1064.34 h60
  text ".Print_Date" at 3119.5,-1064.34 h60
  text ".Print_Time" at 3848.5,-1064.34 h60
  text "TEXAS INSTRUMENTS" at 5113,-1064.34 h60
M12 Stackup:
  drawing of 503 lines, arcs and shapes, not listed
  text "Layer" at 6021.58,6346.5 h60
  text "Name" at 6431.49,6346.5 h60
  text "Material" at 7361.23,6346.5 h60
  text "Thickness" at 8221,6346.5 h60
  text "Constant" at 8870.84,6346.5 h60
  text "Board Layer Stack" at 9440.7,6346.5 h60
  text "1" at 6021.58,6226.5 h60
  text "Top Overlay" at 6431.49,6226.5 h60
  text "2" at 6021.58,6106.5 h60
  text "Top Solder" at 6431.49,6106.5 h60
  text "Solder Resist" at 7361.23,6106.5 h60
  text "0.45mil" at 8221,6106.5 h60
  text "3" at 8870.84,6106.5 h60
  text "3" at 6021.58,5986.5 h60
  text "SSTXRX1" at 6431.49,5986.5 h60
  text "Copper" at 7361.23,5986.5 h60
  text "1.40mil" at 8221,5986.5 h60
  text "4" at 6021.58,5866.5 h60
  text "Dielectric1" at 6431.49,5866.5 h60
  text "FR-4" at 7361.23,5866.5 h60
  text "4.92mil" at 8221,5866.5 h60
  text "4.1" at 8870.84,5866.5 h60
  text "5" at 6021.58,5746.5 h60
  text "GND Plane 1" at 6431.49,5746.5 h60
  text "Copper" at 7361.23,5746.5 h60
  text "0.70mil" at 8221,5746.5 h60
  text "6" at 6021.58,5626.5 h60
  text "Dielectric 2" at 6431.49,5626.5 h60
  text "FR-4" at 7361.23,5626.5 h60
  text "7.87mil" at 8221,5626.5 h60
  text "4.1" at 8870.84,5626.5 h60
  text "7" at 6021.58,5506.5 h60
  text "High Speed" at 6431.49,5506.5 h60
  text "Copper" at 7361.23,5506.5 h60
  text "0.70mil" at 8221,5506.5 h60
  text "8" at 6021.58,5386.5 h60
  text "Dielectric 3" at 6431.49,5386.5 h60
  text "FR-4" at 7361.23,5386.5 h60
  text "7.87mil" at 8221,5386.5 h60
  text "4.1" at 8870.84,5386.5 h60
  text "9" at 6021.58,5266.5 h60
  text "GND Plane 2" at 6431.49,5266.5 h60
  text "Copper" at 7361.23,5266.5 h60
  text "0.70mil" at 8221,5266.5 h60
  text "10" at 6021.58,5146.5 h60
  text "Dielectric 4" at 6431.49,5146.5 h60
  text "FR-4" at 7361.23,5146.5 h60
  text "9.80mil" at 8221,5146.5 h60
  text "4.1" at 8870.84,5146.5 h60
  text "11" at 6021.58,5026.5 h60
  text "Power 1" at 6431.49,5026.5 h60
  text "Copper" at 7361.23,5026.5 h60
  text "0.70mil" at 8221,5026.5 h60
  text "12" at 6021.58,4906.5 h60
  text "Dielectric 5" at 6431.49,4906.5 h60
  text "FR-4" at 7361.23,4906.5 h60
  text "7.87mil" at 8221,4906.5 h60
  text "4.1" at 8870.84,4906.5 h60
  text "13" at 6021.58,4786.5 h60
  text "Power 2" at 6431.49,4786.5 h60
  text "Copper" at 7361.23,4786.5 h60
  text "0.70mil" at 8221,4786.5 h60
  text "14" at 6021.58,4666.5 h60
  text "Dielectric 6" at 6431.49,4666.5 h60
  text "FR-4" at 7361.23,4666.5 h60
  text "7.87mil" at 8221,4666.5 h60
  text "4.1" at 8870.84,4666.5 h60
  text "15" at 6021.58,4546.5 h60
  text "GND Plane 3" at 6431.49,4546.5 h60
  text "Copper" at 7361.23,4546.5 h60
  text "0.70mil" at 8221,4546.5 h60
  text "16" at 6021.58,4426.5 h60
  text "Dielectric 7" at 6431.49,4426.5 h60
  text "FR-4" at 7361.23,4426.5 h60
  text "4.92mil" at 8221,4426.5 h60
  text "4.1" at 8870.84,4426.5 h60
  text "17" at 6021.58,4306.5 h60
  text "SSTXRX2" at 6431.49,4306.5 h60
  text "Copper" at 7361.23,4306.5 h60
  text "1.40mil" at 8221,4306.5 h60
  text "18" at 6021.58,4186.5 h60
  text "Bottom Solder" at 6431.49,4186.5 h60
  text "Solder Resist" at 7361.23,4186.5 h60
  text "0.45mil" at 8221,4186.5 h60
  text "3" at 8870.84,4186.5 h60
  text "19" at 6021.58,4066.5 h60
  text "Bottom Overlay" at 6431.49,4066.5 h60
  text ".Layer_Name" at 577,-858.49 h60
M13 Component Bodies Top:
  text ".Layer_Name" at 577,-858.49 h60
M14 Component Bodies Bottom:
  text ".Layer_Name" at 577,-858.49 h60
M15 Courtyards Top:
  text ".Layer_Name" at 577,-858.49 h60
M16 Courtyards Bottom:
  text ".Layer_Name" at 577,-858.49 h60
Drill Drawing:
  drawing of 152 lines, arcs and shapes, not listed
  text "Symbol" at 5345.77,3385.59 h72
  text "Quantity" at 5631.52,3385.59 h72
  text "Finished Hole Size" at 5948.7,3385.59 h72
  text "Plated" at 6570.45,3385.59 h72
  text "Hole Type" at 6814.77,3385.59 h72
  text "Drill Layer Pair" at 7175.11,3385.59 h72
  text "Hole Tolerance" at 7767.18,3385.59 h72
  text "51" at 5631.52,3285.96 h60
  text "7.87mil (0.200mm)" at 5948.7,3285.96 h60
  text "PTH" at 6570.45,3285.96 h60
  text "Round" at 6814.77,3285.96 h60
  text "SSTXRX1 - SSTXRX2" at 7175.11,3285.96 h60
  text "581" at 5631.52,3186.34 h60
  text "8.00mil (0.203mm)" at 5948.7,3186.34 h60
  text "PTH" at 6570.45,3186.34 h60
  text "Round" at 6814.77,3186.34 h60
  text "SSTXRX1 - SSTXRX2" at 7175.11,3186.34 h60
  text "3" at 5631.52,3086.72 h60
  text "12.00mil (0.305mm)" at 5948.7,3086.72 h60
  text "PTH" at 6570.45,3086.72 h60
  text "Round" at 6814.77,3086.72 h60
  text "SSTXRX1 - SSTXRX2" at 7175.11,3086.72 h60
  text "28" at 5631.52,2987.1 h60
  text "15.75mil (0.400mm)" at 5948.7,2987.1 h60
  text "PTH" at 6570.45,2987.1 h60
  text "Round" at 6814.77,2987.1 h60
  text "SSTXRX1 - SSTXRX2" at 7175.11,2987.1 h60
  text "3" at 5631.52,2887.47 h60
  text "40.00mil (1.016mm)" at 5948.7,2887.47 h60
  text "PTH" at 6570.45,2887.47 h60
  text "Round" at 6814.77,2887.47 h60
  text "SSTXRX1 - SSTXRX2" at 7175.11,2887.47 h60
  text "16" at 5631.52,2787.85 h60
  text "40.16mil (1.020mm)" at 5948.7,2787.85 h60
  text "PTH" at 6570.45,2787.85 h60
  text "Round" at 6814.77,2787.85 h60
  text "SSTXRX1 - SSTXRX2" at 7175.11,2787.85 h60
  text "8" at 5631.52,2688.23 h60
  text "23.62mil (0.600mm)" at 5948.7,2688.23 h60
  text "PTH" at 6570.45,2688.23 h60
  text "Slot" at 6814.77,2688.23 h60
  text "SSTXRX1 - SSTXRX2" at 7175.11,2688.23 h60
  text "1" at 5631.52,2588.61 h60
  text "23.62mil (0.600mm)" at 5948.7,2588.61 h60
  text "PTH" at 6570.45,2588.61 h60
  text "Slot" at 6814.77,2588.61 h60
  text "SSTXRX1 - SSTXRX2" at 7175.11,2588.61 h60
  text "+/-1.97mil" at 7767.18,2588.61 h60
  text "2" at 5631.52,2488.98 h60
  text "23.62mil (0.600mm)" at 5948.7,2488.98 h60
  text "PTH" at 6570.45,2488.98 h60
  text "Slot" at 6814.77,2488.98 h60
  text "SSTXRX1 - SSTXRX2" at 7175.11,2488.98 h60
  text "+/-1.97mil" at 7767.18,2488.98 h60
  text "2" at 5631.52,2389.36 h60
  text "25.59mil (0.650mm)" at 5948.7,2389.36 h60
  text "PTH" at 6570.45,2389.36 h60
  text "Slot" at 6814.77,2389.36 h60
  text "SSTXRX1 - SSTXRX2" at 7175.11,2389.36 h60
  text "2" at 5631.52,2289.74 h60
  text "27.56mil (0.700mm)" at 5948.7,2289.74 h60
  text "PTH" at 6570.45,2289.74 h60
  text "Slot" at 6814.77,2289.74 h60
  text "SSTXRX1 - SSTXRX2" at 7175.11,2289.74 h60
  text "+/-1.97mil" at 7767.18,2289.74 h60
  text "2" at 5631.52,2190.12 h60
  text "27.56mil (0.700mm)" at 5948.7,2190.12 h60
  text "PTH" at 6570.45,2190.12 h60
  text "Slot" at 6814.77,2190.12 h60
  text "SSTXRX1 - SSTXRX2" at 7175.11,2190.12 h60
  text "+/-1.97mil" at 7767.18,2190.12 h60
  text "2" at 5631.52,2090.5 h60
  text "31.50mil (0.800mm)" at 5948.7,2090.5 h60
  text "PTH" at 6570.45,2090.5 h60
  text "Slot" at 6814.77,2090.5 h60
  text "SSTXRX1 - SSTXRX2" at 7175.11,2090.5 h60
  text "+/-1.97mil" at 7767.18,2090.5 h60
  text "2" at 5631.52,1990.87 h60
  text "32.48mil (0.825mm)" at 5948.7,1990.87 h60
  text "PTH" at 6570.45,1990.87 h60
  text "Slot" at 6814.77,1990.87 h60
  text "SSTXRX1 - SSTXRX2" at 7175.11,1990.87 h60
  text "703 Total" at 5631.52,1891.25 h60
  text "Slot definitions :" at 5345.77,1811.64 h60
  text "Routed Path Length" at 5789.08,1811.64 h60
  text "= Calculated from tool start centre position to tool end centre position." at 6321.41,1811.64 h60
  text "Hole Length" at 5789.08,1761.91 h60
  text "= Routed Path Length + Tool Size = Slot length as defined in the PCB layout" at 6121.61,1761.91 h60
  text ".Layer_Name" at 577,-858.49 h60
M17 Embedded Cavity:
  text ".Layer_Name" at 577,-858.49 h60
M18 Embedded Assembly:
  text ".Layer_Name" at 577,-858.49 h60
M19 Embedded Keepout:
  text ".Layer_Name" at 577,-858.49 h60

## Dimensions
0,0 to 2080,0 on M2 Board Dimensions
0,0 to 0,2700 on M2 Board Dimensions
0,-400 to 1000,-400 on M2 Board Dimensions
